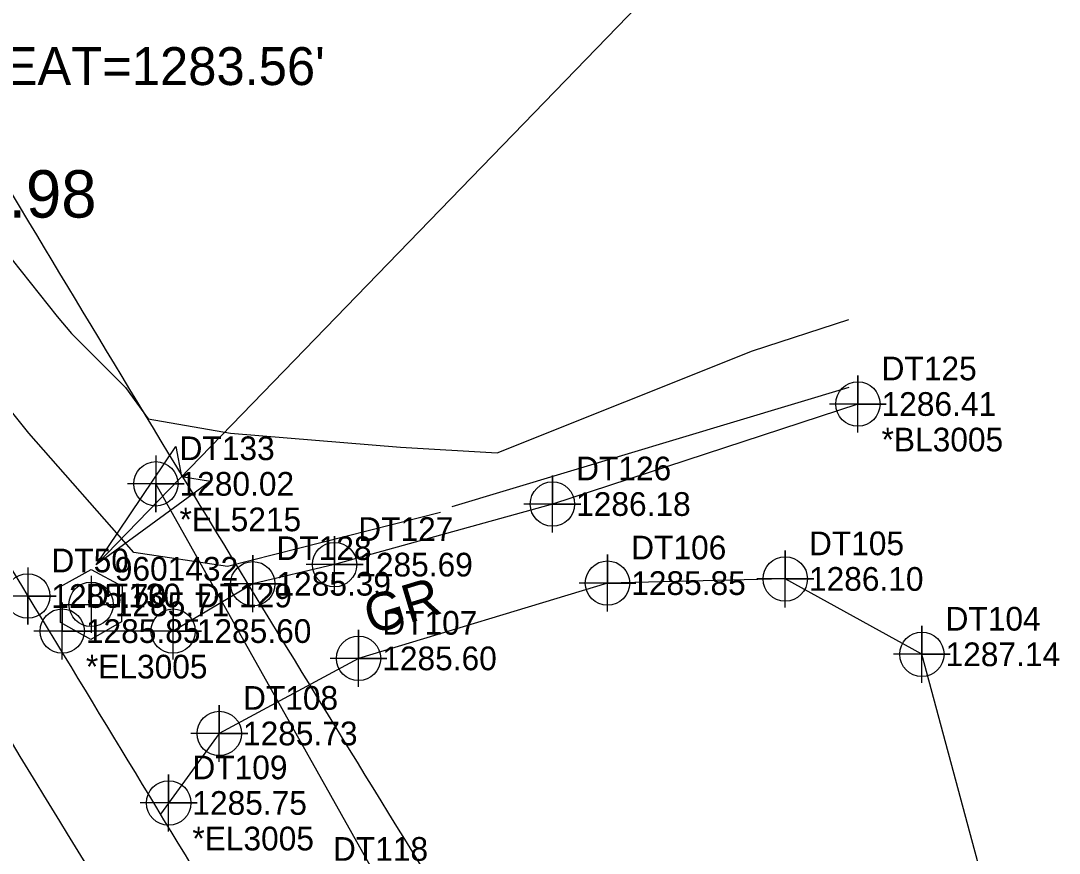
# Model space of a CAD drawing. Extents: x 1393723 to 1394549, y 957573 to 958412.
# Drawn here: x 1394252.2 to 1394361.8, y 958015.1 to 958102.9 of the extents above; entities that cross this region are included whole.
import ezdxf

# ---------------------------------------------------------------- set-up
doc = ezdxf.new("R2010")
doc.units = 0
for name, color, linetype in [('Cogo Default Point CELL', 7, 'Continuous'), ('COGO Default Point Elevation', 7, 'Continuous'), ('COGO Default Point Number', 7, 'Continuous'), ('CTL GPS Vertical CELL', 7, 'Continuous'), ('CTL GPS Vertical Cogo Elevation', 7, 'Continuous'), ('CTL GPS Vertical Cogo Number', 7, 'Continuous'), ('Default', 7, 'Continuous'), ('Exist Horizontal Alignment', 7, 'Continuous'), ('Exist Right of Way Line', 7, 'Continuous'), ('Exist Roads EOP', 7, 'Continuous'), ('Exist Roads EOP Cogo Elevation', 7, 'Continuous'), ('Exist Roads EOP Cogo Number', 7, 'Continuous'), ('Exist Roads EOP Cogo Point CELL', 7, 'Continuous'), ('Exist Roads Soil', 7, 'Continuous'), ('Exist Roads Soil Cogo Comment', 7, 'Continuous'), ('Exist Roads Soil Cogo Elevation', 7, 'Continuous'), ('Exist Roads Soil Cogo Number', 7, 'Continuous'), ('Exist Roads Soil Cogo Point CELL', 7, 'Continuous'), ('Exist Roads Soil Text', 7, 'Continuous'), ('Exist Structure Major Bridge Seat Top Elevation', 7, 'Continuous'), ('Exist Structure Major Deck Tunnel Box Culvert Cogo Elevation', 7, 'Continuous'), ('Exist Structure Minor Pipes CMP 15 Inch', 7, 'Continuous'), ('Exist Structure Minor Pipes CMP 15 Inch Cogo Comment', 7, 'Continuous'), ('Exist Structure Minor Pipes CMP 15 Inch Cogo Elevation', 7, 'Continuous'), ('Exist Structure Minor Pipes CMP 15 Inch Cogo Number', 7, 'Continuous'), ('Exist Structure Minor Pipes CMP 15 Inch Cogo Point CELL', 7, 'Continuous'), ('Exist Vegetation Hedge Row', 7, 'Continuous'), ('Exist Vegetation Shrub Cogo Number', 7, 'Continuous'), ('Old_Level_11', 7, 'Continuous')]:
    doc.layers.add(name, color=color, linetype=linetype)

msp = doc.modelspace()

# ---------------------------------------------------------------- linework, layer by layer
at = {"layer": 'Cogo Default Point CELL'}
for points in [[(1394259.67, 958044.38), (1394259.67, 958041.38)], [(1394256.67, 958041.38), (1394259.67, 958041.38)], [(1394259.67, 958041.38), (1394262.67, 958041.38)], [(1394259.67, 958041.38), (1394259.67, 958038.38)]]:
    msp.add_lwpolyline(points, dxfattribs=at)
msp.add_circle((1394259.67, 958041.38), 2.34, dxfattribs=at)
at = {"layer": 'CTL GPS Vertical CELL'}
msp.add_line((1394259.67, 958041.38), (1394259.67, 958041.38), dxfattribs=at)
msp.add_lwpolyline([(1394256.44, 958043.25), (1394259.69, 958045.06), (1394262.94, 958043.28), (1394262.89, 958039.55), (1394259.64, 958037.66), (1394256.44, 958039.48)], close=True, dxfattribs=at)
at = {"layer": 'Default'}
msp.add_lwpolyline([(1394260.2, 958045.54), (1394356.95, 958145.42)], dxfattribs=at)
at = {"layer": 'Exist Horizontal Alignment'}
msp.add_arc((1399628.18, 961309.9), 6300, 210.988188, 211.917005, dxfattribs=at)
at = {"layer": 'Exist Right of Way Line'}
msp.add_line((1394208.88, 958155.31), (1394253.08, 958081.72), dxfattribs=at)
for radius in [6270, 6330]:
    msp.add_arc((1399628.18, 961309.9), radius, 210.988188, 211.917005, dxfattribs=at)
at = {"layer": 'Exist Roads EOP'}
for points in [[(1394231.47, 958077.14), (1394252.98, 958042.26), (1394277.17, 958002.55), (1394302.35, 957962.17), (1394325.75, 957924.49)], [(1394215.84, 958067.9), (1394237.36, 958032.16), (1394261.7, 957991.75), (1394286.48, 957951.93), (1394310.18, 957914.04)]]:
    msp.add_spline(points, degree=3, dxfattribs=at)
at = {"layer": 'Exist Roads EOP Cogo Point CELL'}
msp.add_lwpolyline([(1394252.98, 958045.26), (1394252.98, 958039.26), (1394252.98, 958042.26), (1394255.98, 958042.26), (1394249.98, 958042.26)], dxfattribs=at)
msp.add_circle((1394252.98, 958042.26), 2.34, dxfattribs=at)
at = {"layer": 'Exist Roads Soil'}
for points in [[(1394340.55, 958062.51), (1394308.33, 958051.96), (1394285.35, 958045.57), (1394276.72, 958043.55), (1394268.32, 958038.56), (1394255.26, 958038.56)], [(1394305.86, 957956.52), (1394315.1, 957959.69), (1394333.91, 957973.06), (1394347.22, 957982.77), (1394355.74, 958004.79), (1394347.3, 958036.11), (1394332.89, 958044.06), (1394314.14, 958043.62), (1394287.88, 958035.68), (1394273.19, 958027.76), (1394266.99, 958019.24)]]:
    msp.add_lwpolyline(points, dxfattribs=at)
at = {"layer": 'Exist Roads Soil Cogo Point CELL'}
for points in [[(1394340.55, 958059.51), (1394340.55, 958065.51), (1394340.55, 958062.51), (1394343.55, 958062.51), (1394337.55, 958062.51)], [(1394308.33, 958048.96), (1394308.33, 958054.96), (1394308.33, 958051.96), (1394311.33, 958051.96), (1394305.33, 958051.96)], [(1394285.35, 958042.57), (1394285.35, 958048.57), (1394285.35, 958045.57), (1394288.35, 958045.57), (1394282.35, 958045.57)], [(1394332.89, 958041.06), (1394332.89, 958047.06), (1394332.89, 958044.06), (1394335.89, 958044.06), (1394329.89, 958044.06)], [(1394276.72, 958040.55), (1394276.72, 958046.55), (1394276.72, 958043.55), (1394279.72, 958043.55), (1394273.72, 958043.55)], [(1394314.14, 958040.62), (1394314.14, 958046.62), (1394314.14, 958043.62), (1394317.14, 958043.62), (1394311.14, 958043.62)], [(1394256.62, 958035.56), (1394256.62, 958041.56), (1394256.62, 958038.56), (1394259.62, 958038.56), (1394253.62, 958038.56)], [(1394268.32, 958035.56), (1394268.32, 958041.56), (1394268.32, 958038.56), (1394271.32, 958038.56), (1394265.32, 958038.56)], [(1394347.3, 958033.11), (1394347.3, 958039.11), (1394347.3, 958036.11), (1394350.3, 958036.11), (1394344.3, 958036.11)], [(1394287.88, 958032.68), (1394287.88, 958038.68), (1394287.88, 958035.68), (1394290.88, 958035.68), (1394284.88, 958035.68)], [(1394273.19, 958024.76), (1394273.19, 958030.76), (1394273.19, 958027.76), (1394276.19, 958027.76), (1394270.19, 958027.76)], [(1394267.85, 958017.43), (1394267.85, 958023.43), (1394267.85, 958020.43), (1394270.85, 958020.43), (1394264.85, 958020.43)]]:
    msp.add_lwpolyline(points, dxfattribs=at)
for centre in [(1394340.55, 958062.51), (1394308.33, 958051.96), (1394285.35, 958045.57), (1394276.72, 958043.55), (1394314.14, 958043.62), (1394332.89, 958044.06), (1394256.62, 958038.56), (1394268.32, 958038.56), (1394287.88, 958035.68), (1394347.3, 958036.11), (1394273.19, 958027.76), (1394267.85, 958020.43)]:
    msp.add_circle(centre, 2.34, dxfattribs=at)
at = {"layer": 'Exist Structure Minor Pipes CMP 15 Inch'}
msp.add_line((1394327.62, 957945.35), (1394266.5, 958054.09), dxfattribs=at)
at = {"layer": 'Exist Structure Minor Pipes CMP 15 Inch Cogo Point CELL'}
msp.add_lwpolyline([(1394266.5, 958057.09), (1394266.5, 958051.09), (1394266.5, 958054.09), (1394269.5, 958054.09), (1394263.5, 958054.09)], dxfattribs=at)
msp.add_circle((1394266.5, 958054.09), 2.34, dxfattribs=at)
at = {"layer": 'Exist Vegetation Hedge Row'}
for points in [[(1394296.51, 958051.06), (1394274.06, 958045.36), (1394264.18, 958046.86), (1394253.11, 958059.45), (1394240.84, 958074.73), (1394240.24, 958083.42), (1394246.52, 958086.41), (1394250.41, 958078.92), (1394256.1, 958071.73), (1394257.6, 958069.93), (1394263.28, 958064.24), (1394265.68, 958060.94), (1394274.36, 958059.45), (1394292.32, 958057.95), (1394302.49, 958057.35), (1394329.43, 958068.13), (1394339.61, 958071.43)], [(1394339.61, 958064.24), (1394297.71, 958051.65)]]:
    msp.add_lwpolyline(points, dxfattribs=at)
at = {"layer": 'Old_Level_11'}
msp.add_lwpolyline([(1394272.27, 958054.38), (1394260.2, 958045.54), (1394268.62, 958058.03), (1394269.2, 958054.85)], close=True, dxfattribs=at)

# ---------------------------------------------------------------- texts
at = {"layer": 'COGO Default Point Elevation'}
msp.add_text('1285.71', height=2.5, dxfattribs=at).set_placement((1394262.17, 958040.13))
at = {"layer": 'COGO Default Point Number'}
msp.add_text('9601432', height=2.5, dxfattribs=at).set_placement((1394262.17, 958043.88))
at = {"layer": 'CTL GPS Vertical Cogo Elevation'}
msp.add_text('1285.71', height=2.5, dxfattribs=at).set_placement((1394262.17, 958040.13))
at = {"layer": 'CTL GPS Vertical Cogo Number'}
msp.add_text('9601432', height=2.5, dxfattribs=at).set_placement((1394262.17, 958043.88))
at = {"layer": 'Exist Roads EOP Cogo Elevation'}
msp.add_text('1285.70', height=2.5, dxfattribs=at).set_placement((1394255.48, 958041.01))
at = {"layer": 'Exist Roads EOP Cogo Number'}
msp.add_text('DT50', height=2.5, dxfattribs=at).set_placement((1394255.48, 958044.76))
at = {"layer": 'Exist Roads Soil Cogo Comment'}
for s, p in [('*BL3005', (1394343.05, 958057.51)), ('*EL3005', (1394259.12, 958033.56)), ('*EL3005', (1394270.35, 958015.43))]:
    msp.add_text(s, height=2.5, dxfattribs=at).set_placement(p)
at = {"layer": 'Exist Roads Soil Cogo Elevation'}
for s, p in [('1286.41', (1394343.05, 958061.26)), ('1286.18', (1394310.83, 958050.71)), ('1285.69', (1394287.85, 958044.32)), ('1285.39', (1394279.22, 958042.3)), ('1285.85', (1394316.64, 958042.37)), ('1286.10', (1394335.39, 958042.81)), ('1285.85', (1394259.12, 958037.31)), ('1285.60', (1394270.82, 958037.31)), ('1285.60', (1394290.38, 958034.43)), ('1287.14', (1394349.8, 958034.86)), ('1285.73', (1394275.69, 958026.51)), ('1285.75', (1394270.35, 958019.18))]:
    msp.add_text(s, height=2.5, dxfattribs=at).set_placement(p)
at = {"layer": 'Exist Roads Soil Cogo Number'}
for s, p in [('DT125', (1394343.05, 958065.01)), ('DT126', (1394310.83, 958054.46)), ('DT127', (1394287.85, 958048.07)), ('DT105', (1394335.39, 958046.56)), ('DT128', (1394279.22, 958046.05)), ('DT106', (1394316.64, 958046.12)), ('DT130', (1394259.12, 958041.06)), ('DT129', (1394270.82, 958041.06)), ('DT107', (1394290.38, 958038.18)), ('DT104', (1394349.8, 958038.61)), ('DT108', (1394275.69, 958030.26)), ('DT109', (1394270.35, 958022.93))]:
    msp.add_text(s, height=2.5, dxfattribs=at).set_placement(p)
at = {"layer": 'Exist Roads Soil Text'}
msp.add_text('GR', height=4, rotation=16.8238, dxfattribs=at).set_placement((1394289.2, 958038.17))
at = {"layer": 'Exist Structure Major Bridge Seat Top Elevation'}
msp.add_text("SEAT=1283.56'", height=4, dxfattribs=at).set_placement((1394246.87, 958096.15))
at = {"layer": 'Exist Structure Major Deck Tunnel Box Culvert Cogo Elevation'}
msp.add_text('1284.98', height=5, dxfattribs=at).set_placement((1394236.07, 958082.17))
at = {"layer": 'Exist Structure Minor Pipes CMP 15 Inch Cogo Comment'}
msp.add_text('*EL5215', height=2.5, dxfattribs=at).set_placement((1394269, 958049.09))
at = {"layer": 'Exist Structure Minor Pipes CMP 15 Inch Cogo Elevation'}
msp.add_text('1280.02', height=2.5, dxfattribs=at).set_placement((1394269, 958052.84))
at = {"layer": 'Exist Structure Minor Pipes CMP 15 Inch Cogo Number'}
msp.add_text('DT133', height=2.5, dxfattribs=at).set_placement((1394269, 958056.59))
at = {"layer": 'Exist Vegetation Shrub Cogo Number'}
msp.add_text('DT118', height=2.5, dxfattribs=at).set_placement((1394285.18, 958014.33))

doc.saveas('drawing.dxf')
